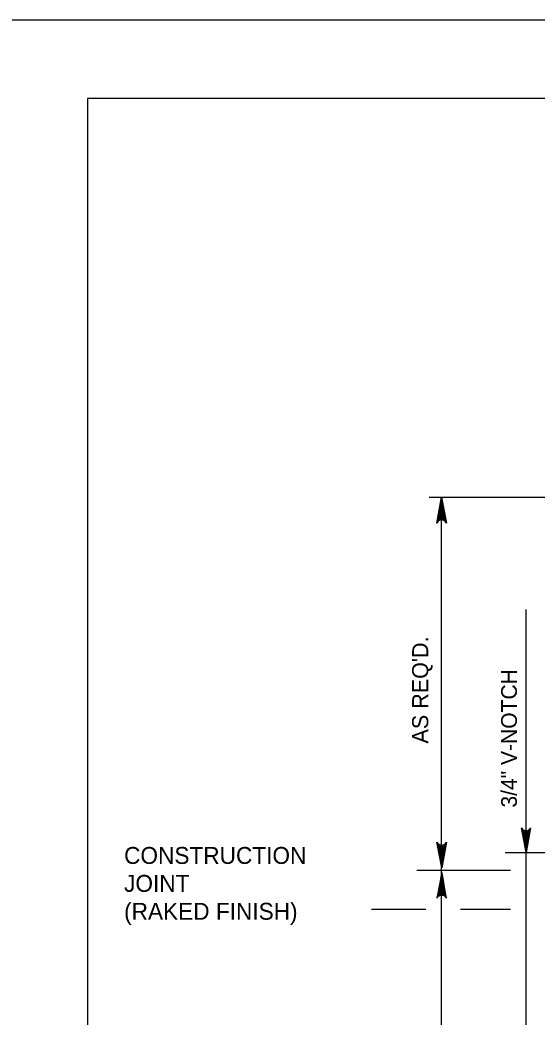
# Model space of a CAD drawing. Extents: x 638167 to 640248, y 296544 to 298920.
# Drawn here: x 639033.9 to 639132.5, y 298730.4 to 298920.5 of the extents above; entities that cross this region are included whole.
import ezdxf

# ---------------------------------------------------------------- set-up
doc = ezdxf.new("R2010")
doc.units = 0
doc.layers.add('1', color=7, linetype='Continuous')
doc.layers.add('PLT-BNDY', color=7, linetype='Continuous')

msp = doc.modelspace()

# ---------------------------------------------------------------- linework, layer by layer
at = {"layer": '1'}
for p, q in [((639832.78, 298905.48), (639046.78, 298905.48)), ((639046.78, 298905.48), (639046.78, 298341.48)), ((639111.88, 298829.48), (639186.85, 298829.48)), ((639114.27, 298758.36), (639114.27, 298829.48)), ((639130.36, 298715.44), (639130.36, 298808.06)), ((639126.41, 298761.75), (639188.31, 298761.75)), ((639109.54, 298758.36), (639127.4, 298758.36)), ((639114.27, 298613.58), (639114.27, 298758.36)), ((639111.25, 298750.84), (639100.93, 298750.84)), ((639127.4, 298750.84), (639117.89, 298750.84))]:
    msp.add_line(p, q, dxfattribs=at)
for points in [[(639114.27, 298829.48), (639115.19, 298824.55), (639115.06, 298824.74), (639114.93, 298824.93), (639114.77, 298825.03), (639114.6, 298825.13), (639114.43, 298825.16), (639114.27, 298825.18), (639114.1, 298825.16), (639113.94, 298825.13), (639113.77, 298825.03), (639113.61, 298824.93), (639113.48, 298824.74), (639113.34, 298824.55), (639114.27, 298829.48), (639113.48, 298824.74), (639113.61, 298824.93), (639114.27, 298829.48), (639113.77, 298825.03), (639113.94, 298825.13), (639114.27, 298829.48), (639114.1, 298825.16), (639114.27, 298825.18), (639114.27, 298829.48), (639114.43, 298825.16), (639114.6, 298825.13), (639114.27, 298829.48), (639114.77, 298825.03), (639114.93, 298824.93), (639114.27, 298829.48), (639115.06, 298824.74)], [(639130.36, 298761.75), (639129.48, 298766.45), (639129.61, 298766.27), (639129.73, 298766.09), (639129.89, 298765.99), (639130.05, 298765.9), (639130.2, 298765.87), (639130.36, 298765.85), (639130.52, 298765.87), (639130.68, 298765.9), (639130.83, 298765.99), (639130.99, 298766.09), (639131.12, 298766.27), (639131.24, 298766.45), (639130.36, 298761.75), (639131.12, 298766.27), (639130.99, 298766.09), (639130.36, 298761.75), (639130.83, 298765.99), (639130.68, 298765.9), (639130.36, 298761.75), (639130.52, 298765.87), (639130.36, 298765.85), (639130.36, 298761.75), (639130.2, 298765.87), (639130.05, 298765.9), (639130.36, 298761.75), (639129.89, 298765.99), (639129.73, 298766.09), (639130.36, 298761.75), (639129.61, 298766.27)], [(639114.3, 298758.78), (639113.37, 298763.72), (639113.51, 298763.53), (639113.64, 298763.34), (639113.8, 298763.24), (639113.97, 298763.14), (639114.13, 298763.11), (639114.3, 298763.08), (639114.46, 298763.11), (639114.63, 298763.14), (639114.79, 298763.24), (639114.96, 298763.34), (639115.09, 298763.53), (639115.22, 298763.72), (639114.3, 298758.78), (639115.09, 298763.53), (639114.96, 298763.34), (639114.3, 298758.78), (639114.79, 298763.24), (639114.63, 298763.14), (639114.3, 298758.78), (639114.46, 298763.11), (639114.3, 298763.08), (639114.3, 298758.78), (639114.13, 298763.11), (639113.97, 298763.14), (639114.3, 298758.78), (639113.8, 298763.24), (639113.64, 298763.34), (639114.3, 298758.78), (639113.51, 298763.53)], [(639114.3, 298757.95), (639113.37, 298753.01), (639113.51, 298753.2), (639113.64, 298753.39), (639113.8, 298753.49), (639113.97, 298753.59), (639114.13, 298753.62), (639114.3, 298753.65), (639114.46, 298753.62), (639114.63, 298753.59), (639114.79, 298753.49), (639114.96, 298753.39), (639115.09, 298753.2), (639115.22, 298753.01), (639114.3, 298757.95), (639115.09, 298753.2), (639114.96, 298753.39), (639114.3, 298757.95), (639114.79, 298753.49), (639114.63, 298753.59), (639114.3, 298757.95), (639114.46, 298753.62), (639114.3, 298753.65), (639114.3, 298757.95), (639114.13, 298753.62), (639113.97, 298753.59), (639114.3, 298757.95), (639113.8, 298753.49), (639113.64, 298753.39), (639114.3, 298757.95), (639113.51, 298753.2)]]:
    msp.add_lwpolyline(points, dxfattribs=at)
at = {"layer": 'PLT-BNDY'}
msp.add_lwpolyline([(639007.78, 298920.48), (639848.78, 298920.48), (639848.78, 298326.48), (639007.78, 298326.48)], close=True, dxfattribs=at)

# ---------------------------------------------------------------- texts
at = {"layer": '1'}
for s, height, p in [("AS REQ'D.", 3.072, (639111.72, 298782.51)), ('3/4" V-NOTCH', 3, (639128.62, 298770.3))]:
    msp.add_text(s, height=height, rotation=90, dxfattribs=at).set_placement(p)
for s, height, p in [('CONSTRUCTION', 3.2256, (639053.75, 298759.56)), ('JOINT', 3.226, (639053.75, 298754.23)), ('(RAKED FINISH)', 3.2256, (639053.75, 298748.91))]:
    msp.add_text(s, height=height, dxfattribs=at).set_placement(p)

doc.saveas('drawing.dxf')
